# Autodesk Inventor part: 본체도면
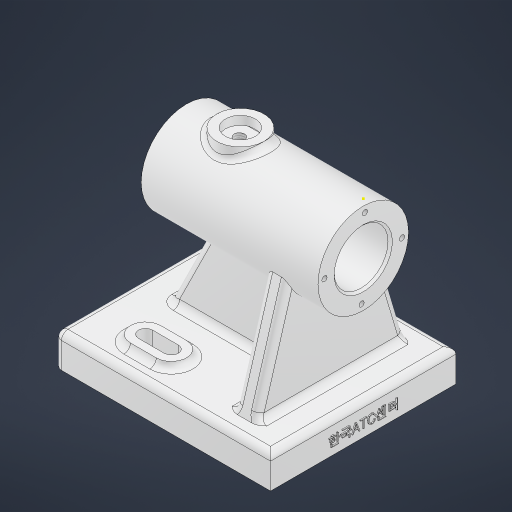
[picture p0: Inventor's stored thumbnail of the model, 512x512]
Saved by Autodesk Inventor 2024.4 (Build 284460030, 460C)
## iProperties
Created: 2026-09
Part Number: 본체도면
Material: 알루미늄 6061
Document SubType Name: Modeling
Designer: user
Density: 2.7 g/cm^3
Appearance: 알루미늄 - 평지
Mass: 625.029 g
Surface Area: 518.945 cm^2
Volume: 231.492 cm^3
Author: user
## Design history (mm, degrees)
sketch "스케치1"
  geometry: L1 (-82, 72)-(0, 72); L2 (-82, 93)-(0, 93); L3 (0, 93)-(0, 84.5); L4 (0, 84.5)-(-20, 84.5); L5 (-20, 84.5)-(-20, 86.5); L6 (-20, 86.5)-(-82, 86.5); L7 (-82, 86.5)-(-82, 93); 2 further points
  constraints: 14 end point, 5 perpendicular, 3 vertical alignment, 2 horizontal, 1 midpoint
  dimensions: "d0" = 82 distance of L1.start L1.end; "d1" = 72 distance from line of L1 point (0, 0); "d2" = 42 diameter of L2 L1; "d3" = 25 diameter of L4 L1; "d4" = 29 diameter of L6 L1; "d6" = 62 distance between parallel lines of L7 L5
revolve "회전1" sketch "스케치1" stored, may be unused: angle "d7" = 90 deg
sketch "스케치2"
  geometry: L1 (0, 0)-(0, 43); L2 (0, 43)-(100, 43); L3 (100, 43)-(100, -43); L4 (100, -43)-(0, -43); L5 (0, -43)-(0, 43); L6 (82, 21)-(82, -21) reference; 3 further points
  constraints: 10 end point, 3 perpendicular, 2 midpoint, 2 vertical, 1 horizontal alignment, 1 point on line
  dimensions: "d8" = 100 distance of L1.end L2.end; "d9" = 86 distance between parallel lines of L4 L2
extrude "돌출1" join sketch "스케치2" distance "d10" = 15; taper "d11" = 0 deg
sketch "스케치3"
  geometry: L1 (-100, 43)-(-100, -43) reference; L2 (0, 0)-(-100, 0); L3 (-62, 34)-(-74, 34); L4 (-74, 20)-(-62, 20); A1 r 7 centre (-74, 27) between (-74, 34) and (-74, 20); A2 r 7 centre (-62, 27) between (-62, 20) and (-62, 34)
  constraints: 6 end point, 4 point on circle, 4 tangent, 2 centre point, 1 horizontal, 1 midpoint, 1 parallel
  dimensions: "d15" = 14 distance between parallel lines of L4 L3; "d16" = 54 diameter of A1.centre L2; "d17" = 26 distance from line of A1.centre L1; "d18" = 12 distance of A2.centre A1.centre
extrude "돌출2" join sketch "스케치3" distance "d19" = 3; taper "d20" = 0 deg
sketch "스케치4"
  geometry: L1 (-74, 20)-(-62, 20) reference; L2 (-62, 34)-(-74, 34) reference; L3 (-74, 23.7)-(-62, 23.7); L4 (-62, 30.3)-(-74, 30.3); A1 r 7 centre (-74, 27) between (-74, 34) and (-74, 20) reference; A2 r 7 centre (-62, 27) between (-62, 20) and (-62, 34) reference; A3 r 3.3 centre (-74, 27) between (-74, 30.3) and (-74, 23.7); A4 r 3.3 centre (-62, 27) between (-62, 23.7) and (-62, 30.3); 1 further point
  constraints: 4 end point, 4 point on circle, 2 centre point, 3 other
  dimensions: "d21" = 6.6 distance between parallel lines of L3 L4
extrude "돌출3" cut sketch "스케치4" extent not by distance; stored distance "d22" = 0; taper "d23" = 0 deg
fillet "모깎기1" dims "d24" = 3
node "작업 평면1"
sketch "스케치8"
  geometry: 1 further point
sketch "스케치9"
  geometry: L1 (-82, -21)-(-82, 21) reference; L2 (0, -21)-(0, 21) reference; C1 r 11 at (-57, 0); C2 r 7 at (-57, 0); 2 further points
  constraints: 2 centre point, 1 coincident, 1 horizontal alignment, 1 midpoint
  dimensions: "d46" = 22 diameter of C1; "d47" = 14 diameter of C2; "d48" = 25 distance from line of C1.centre L1
extrude "돌출4" join sketch "스케치9" stored distance "d49" = 10; taper "d50" = 0 deg
sketch "스케치10"
  geometry: 2 further points
hole "구멍1" sketch "스케치10" at (-0.482, 0) diameter "d51" = 4.917; stored, may be unused: countersink angle "d55" = 90 deg, drill point angle "d57" = 118 deg; dims "d52" = 12, "d53" = 4, "d54" = 2, "d56" = 17.1
node "작업 평면2"
sketch "스케치11"
  geometry: L1 (86, 15)-(0, 15) reference; L2 (23.028, 65.511)-(8, 15); L3 (62.972, 65.511)-(78, 15); A1 r 21 centre (43, 72) between (23.028, 65.511) and (62.972, 65.511) reference; 1 further point
  constraints: 4 end point, 2 point on circle, 2 point on line, 1 equal length
  dimensions: "d59" = 8 distance of L1.end L2.end; "d60" = 8 distance of L3.end L1.start (= d59)
extrude "돌출5" join sketch "스케치11" distance "d61" = 10; taper "d62" = 0 deg
sketch "스케치13"
  geometry: L1 (-82, 51)-(0, 51) reference; L2 (0, 15)-(-100, 15) reference; L3 (-67.176, 51)-(-85, 15); L4 (-67.176, 51)-(-25, 51); L5 (-25, 65.511)-(-25, 15) reference; L6 (-25, 15)-(-85, 15); 1 further point
  constraints: 6 end point, 4 point on line, 1 collinear
  dimensions: "d65" = 15 distance of L2.end L3.end
extrude "돌출6" join sketch "스케치13" stored distance "d66" = 10; taper "d67" = 0 deg
fillet "모깎기2" dims "d68" = 3
fillet "모깎기3" dims "d69" = 3
fillet "모깎기4" dims "d70" = 3
sketch "스케치14" dims "d78" = 36
  geometry: C1 r 21 at (0, 0) reference; 3 further points
  constraints: 1 coincident, 3 other
hole "구멍2" sketch "스케치14" at (-0.788, 17.983) diameter "d71" = 2.459; stored, may be unused: countersink angle "d75" = 90 deg, drill point angle "d77" = 118 deg; dims "d72" = 8, "d73" = 4, "d74" = 2, "d76" = 10
chamfer "모따기1" distance "d85" = 1; stored, may be unused: second distance "d86" = 2, angle "d87" = 45 deg
chamfer "모따기2" distance "d88" = 1; stored, may be unused: second distance "d89" = 2, angle "d90" = 45 deg
node "작업 평면3"
sketch "스케치15"
  geometry: 1 further point
sketch "스케치16"
  geometry: L1 (0, 0)-(86, 0) reference; 3 further points
  constraints: 1 midpoint, 1 vertical alignment, 1 other
  dimensions: "d92" = 6 distance from line of point (43, 6) L1
feature "엠보싱1" sketch "스케치16" dims "d0" = 82, "d1" = 72, "d2" = 42, "d3" = 25, "d4" = 29, "d6" = 62, "d93" = 0.5, "d94" = 0
sketch "스케치18"
  geometry: C1 r 7 at (-57, 0) reference; C2 r 7 at (-57, 0); 1 further point
  constraints: 1 centre point, 1 coincident
extrude "돌출7" cut sketch "스케치18" distance "d96" = 4; taper "d97" = 0 deg
node "솔리드1"
mirror "미러1"
pattern_circular "원형 패턴2" dims angle "d83" = 360 deg
mirror "미러2"
node "투영된 루프2"
feature "A9D066F2-1C7D-4E18-AEED-F7BC21143FA4" dims "d51" = 4.917, "d52" = 12, "d53" = 4, "d54" = 2, "d55" = 90 deg, "d56" = 17.1, "d57" = 118 deg
other parameters: "d45" = -96, "d58" = -15, "d91" = -41
